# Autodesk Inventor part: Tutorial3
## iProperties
Shininess: 77.0
Length Units: 11269
Angle Units: 11279
Time Units: 11290
Mass Units: 11283
Length Display Precision: 3
Angle Display Precision: 2
Created: 2001-12
Part Number: Tutorial3
Document SubType Name: Modeling
Designer: Renu Muthoo
Density: 0.0
Volumn: 0.0
Area: 0.0
PropertySet Name: Model Information
Control State: 0
Master: False
Checked Out: False
Author: Renu Muthoo
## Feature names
1. Extrusion1
2. Extrusion2
3. Hole4
4. Circular Pattern3
5. Extrusion3
6. Hole5
7. Circular Pattern4
8. Hole6
